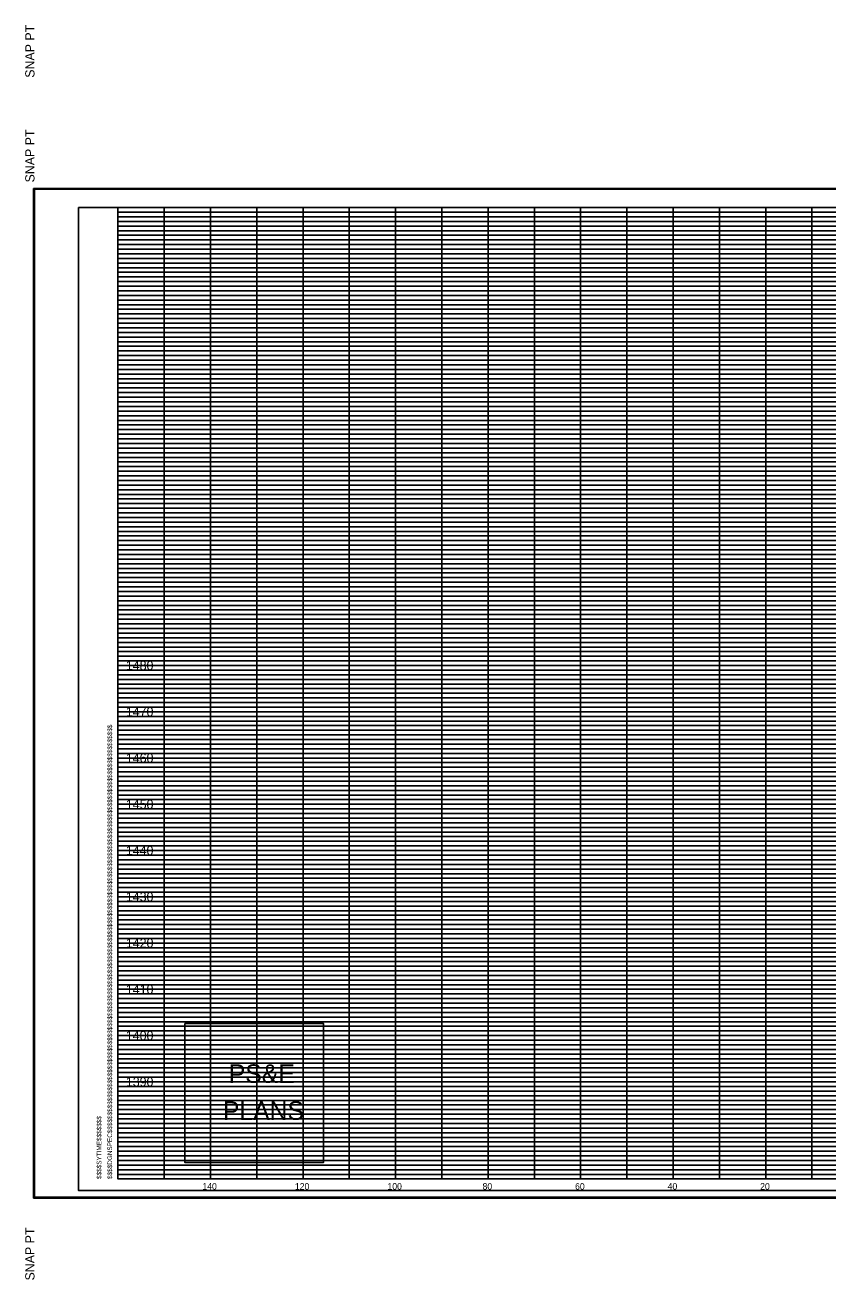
# Model space of a CAD drawing. Extents: x 980 to 2064, y 978 to 2267.
# Drawn here: x 1719.9 to 1893.4, y 978.2 to 1249.4 of the extents above; entities that cross this region are included whole.
import ezdxf

# ---------------------------------------------------------------- set-up
doc = ezdxf.new("R2010")
doc.units = 0
for name, color, linetype in [('Default', 7, 'Continuous'), ('DESIGN - SHEET - Corner Text', 7, 'Continuous'), ('DESIGN - SHEET - Light Grid', 7, 'Continuous'), ('DESIGN - SHEET - Linework', 7, 'Continuous'), ('DESIGN - SHEET - Plot Shape', 7, 'Continuous')]:
    doc.layers.add(name, color=color, linetype=linetype)

# ---------------------------------------------------------------- blocks, each defined once
blk = doc.blocks.new('XSTSHT')
at = {"layer": 'DESIGN - SHEET - Light Grid'}
for p, q in [((0, 20.9), (8, 20.9)), ((8, 20.9), (16, 20.9)), ((0, 20.8), (8, 20.8)), ((0, 20.7), (8, 20.7)), ((8, 20.8), (16, 20.8)), ((8, 20.7), (16, 20.7)), ((0, 20.6), (8, 20.6)), ((0, 20.5), (8, 20.5)), ((0, 20.4), (8, 20.4)), ((8, 20.6), (16, 20.6)), ((8, 20.5), (16, 20.5)), ((8, 20.4), (16, 20.4)), ((0, 20.3), (8, 20.3)), ((0, 20.2), (8, 20.2)), ((0, 20.1), (8, 20.1)), ((8, 20.3), (16, 20.3)), ((8, 20.2), (16, 20.2)), ((8, 20.1), (16, 20.1)), ((0, 19.9), (8, 19.9)), ((8, 19.9), (16, 19.9)), ((0, 19.8), (8, 19.8)), ((0, 19.7), (8, 19.7)), ((0, 19.6), (8, 19.6)), ((8, 19.8), (16, 19.8)), ((8, 19.7), (16, 19.7)), ((8, 19.6), (16, 19.6)), ((0, 19.5), (8, 19.5)), ((0, 19.4), (8, 19.4)), ((0, 19.3), (8, 19.3)), ((8, 19.5), (16, 19.5)), ((8, 19.4), (16, 19.4)), ((8, 19.3), (16, 19.3)), ((0, 19.2), (8, 19.2)), ((0, 19.1), (8, 19.1)), ((8, 19.2), (16, 19.2)), ((8, 19.1), (16, 19.1)), ((0, 18.9), (8, 18.9)), ((0, 18.8), (8, 18.8)), ((8, 18.9), (16, 18.9)), ((8, 18.8), (16, 18.8)), ((0, 18.7), (8, 18.7)), ((0, 18.6), (8, 18.6)), ((0, 18.5), (8, 18.5)), ((8, 18.7), (16, 18.7)), ((8, 18.6), (16, 18.6)), ((8, 18.5), (16, 18.5)), ((0, 18.4), (8, 18.4)), ((0, 18.3), (8, 18.3)), ((0, 18.2), (8, 18.2)), ((8, 18.4), (16, 18.4)), ((8, 18.3), (16, 18.3)), ((8, 18.2), (16, 18.2)), ((0, 18.1), (8, 18.1)), ((8, 18.1), (16, 18.1)), ((0, 17.9), (8, 17.9)), ((0, 17.8), (8, 17.8)), ((0, 17.7), (8, 17.7)), ((8, 17.9), (16, 17.9)), ((8, 17.8), (16, 17.8)), ((8, 17.7), (16, 17.7)), ((0, 17.6), (8, 17.6)), ((0, 17.5), (8, 17.5)), ((0, 17.4), (8, 17.4)), ((8, 17.6), (16, 17.6)), ((8, 17.5), (16, 17.5)), ((8, 17.4), (16, 17.4)), ((0, 17.3), (8, 17.3)), ((0, 17.2), (8, 17.2)), ((0, 17.1), (8, 17.1)), ((8, 17.3), (16, 17.3)), ((8, 17.2), (16, 17.2)), ((8, 17.1), (16, 17.1)), ((0, 16.9), (8, 16.9)), ((8, 16.9), (16, 16.9)), ((0, 16.8), (8, 16.8)), ((0, 16.7), (8, 16.7)), ((0, 16.6), (8, 16.6)), ((8, 16.8), (16, 16.8)), ((8, 16.7), (16, 16.7)), ((8, 16.6), (16, 16.6)), ((0, 16.5), (8, 16.5)), ((0, 16.4), (8, 16.4)), ((0, 16.3), (8, 16.3)), ((8, 16.5), (16, 16.5)), ((8, 16.4), (16, 16.4)), ((8, 16.3), (16, 16.3)), ((0, 16.2), (8, 16.2)), ((0, 16.1), (8, 16.1)), ((8, 16.2), (16, 16.2)), ((8, 16.1), (16, 16.1)), ((0, 15.9), (8, 15.9)), ((0, 15.8), (8, 15.8)), ((8, 15.9), (16, 15.9)), ((8, 15.8), (16, 15.8)), ((0, 15.7), (8, 15.7)), ((0, 15.6), (8, 15.6)), ((0, 15.5), (8, 15.5)), ((8, 15.7), (16, 15.7)), ((8, 15.6), (16, 15.6)), ((8, 15.5), (16, 15.5)), ((0, 15.4), (8, 15.4)), ((0, 15.3), (8, 15.3)), ((0, 15.2), (8, 15.2)), ((8, 15.4), (16, 15.4)), ((8, 15.3), (16, 15.3)), ((8, 15.2), (16, 15.2)), ((0, 15.1), (8, 15.1)), ((8, 15.1), (16, 15.1)), ((0, 14.9), (8, 14.9)), ((0, 14.8), (8, 14.8)), ((0, 14.7), (8, 14.7)), ((8, 14.9), (16, 14.9)), ((8, 14.8), (16, 14.8)), ((8, 14.7), (16, 14.7)), ((0, 14.6), (8, 14.6)), ((0, 14.5), (8, 14.5)), ((0, 14.4), (8, 14.4)), ((8, 14.6), (16, 14.6)), ((8, 14.5), (16, 14.5)), ((8, 14.4), (16, 14.4)), ((0, 14.3), (8, 14.3)), ((0, 14.2), (8, 14.2)), ((8, 14.3), (16, 14.3)), ((8, 14.2), (16, 14.2)), ((0, 14.1), (8, 14.1)), ((0, 13.9), (8, 13.9)), ((8, 14.1), (16, 14.1)), ((8, 13.9), (16, 13.9)), ((0, 13.8), (8, 13.8)), ((0, 13.7), (8, 13.7)), ((0, 13.6), (8, 13.6)), ((8, 13.8), (16, 13.8)), ((8, 13.7), (16, 13.7)), ((8, 13.6), (16, 13.6)), ((0, 13.5), (8, 13.5)), ((0, 13.4), (8, 13.4)), ((0, 13.3), (8, 13.3)), ((8, 13.5), (16, 13.5)), ((8, 13.4), (16, 13.4)), ((8, 13.3), (16, 13.3)), ((0, 13.2), (8, 13.2)), ((0, 13.1), (8, 13.1)), ((8, 13.2), (16, 13.2)), ((8, 13.1), (16, 13.1)), ((0, 12.9), (8, 12.9)), ((0, 12.8), (8, 12.8)), ((8, 12.9), (16, 12.9)), ((8, 12.8), (16, 12.8)), ((0, 12.7), (8, 12.7)), ((0, 12.6), (8, 12.6)), ((0, 12.5), (8, 12.5)), ((8, 12.7), (16, 12.7)), ((8, 12.6), (16, 12.6)), ((8, 12.5), (16, 12.5)), ((0, 12.4), (8, 12.4)), ((0, 12.3), (8, 12.3)), ((8, 12.4), (16, 12.4)), ((8, 12.3), (16, 12.3)), ((0, 12.2), (8, 12.2)), ((0, 12.1), (8, 12.1)), ((8, 12.2), (16, 12.2)), ((8, 12.1), (16, 12.1)), ((0, 11.9), (8, 11.9)), ((0, 11.8), (8, 11.8)), ((0, 11.7), (8, 11.7)), ((8, 11.9), (16, 11.9)), ((8, 11.8), (16, 11.8)), ((8, 11.7), (16, 11.7)), ((0, 11.6), (8, 11.6)), ((0, 11.5), (8, 11.5)), ((0, 11.4), (8, 11.4)), ((8, 11.6), (16, 11.6)), ((8, 11.5), (16, 11.5)), ((8, 11.4), (16, 11.4)), ((0, 11.3), (8, 11.3)), ((0, 11.2), (8, 11.2)), ((8, 11.3), (16, 11.3)), ((8, 11.2), (16, 11.2)), ((0, 11.1), (8, 11.1)), ((0, 10.9), (8, 10.9)), ((8, 11.1), (16, 11.1)), ((8, 10.9), (16, 10.9)), ((0, 10.8), (8, 10.8)), ((0, 10.7), (8, 10.7)), ((0, 10.6), (8, 10.6)), ((8, 10.8), (16, 10.8)), ((8, 10.7), (16, 10.7)), ((8, 10.6), (16, 10.6)), ((0, 10.5), (8, 10.5)), ((0, 10.4), (8, 10.4)), ((8, 10.5), (16, 10.5)), ((8, 10.4), (16, 10.4)), ((0, 10.3), (8, 10.3)), ((0, 10.2), (8, 10.2)), ((0, 10.1), (8, 10.1)), ((8, 10.3), (16, 10.3)), ((8, 10.2), (16, 10.2)), ((8, 10.1), (16, 10.1)), ((0, 9.9), (8, 9.9)), ((0, 9.8), (8, 9.8)), ((8, 9.9), (16, 9.9)), ((8, 9.8), (16, 9.8)), ((0, 9.7), (8, 9.7)), ((0, 9.6), (8, 9.6)), ((0, 9.5), (8, 9.5)), ((8, 9.7), (16, 9.7)), ((8, 9.6), (16, 9.6)), ((8, 9.5), (16, 9.5)), ((0, 9.4), (8, 9.4)), ((0, 9.3), (8, 9.3)), ((8, 9.4), (16, 9.4)), ((8, 9.3), (16, 9.3)), ((0, 9.2), (8, 9.2)), ((0, 9.1), (8, 9.1)), ((8, 9.2), (16, 9.2)), ((8, 9.1), (16, 9.1)), ((0, 8.9), (8, 8.9)), ((0, 8.8), (8, 8.8)), ((0, 8.7), (8, 8.7)), ((8, 8.9), (16, 8.9)), ((8, 8.8), (16, 8.8)), ((8, 8.7), (16, 8.7)), ((0, 8.6), (8, 8.6)), ((0, 8.5), (8, 8.5)), ((8, 8.6), (16, 8.6)), ((8, 8.5), (16, 8.5)), ((0, 8.4), (8, 8.4)), ((0, 8.3), (8, 8.3)), ((0, 8.2), (8, 8.2)), ((8, 8.4), (16, 8.4)), ((8, 8.3), (16, 8.3)), ((8, 8.2), (16, 8.2)), ((0, 8.1), (8, 8.1)), ((0, 7.9), (8, 7.9)), ((8, 8.1), (16, 8.1)), ((8, 7.9), (16, 7.9)), ((0, 7.8), (8, 7.8)), ((0, 7.7), (8, 7.7)), ((0, 7.6), (8, 7.6)), ((8, 7.8), (16, 7.8)), ((8, 7.7), (16, 7.7)), ((8, 7.6), (16, 7.6)), ((0, 7.5), (8, 7.5)), ((0, 7.4), (8, 7.4)), ((8, 7.5), (16, 7.5)), ((8, 7.4), (16, 7.4)), ((0, 7.3), (8, 7.3)), ((0, 7.2), (8, 7.2)), ((0, 7.1), (8, 7.1)), ((8, 7.3), (16, 7.3)), ((8, 7.2), (16, 7.2)), ((8, 7.1), (16, 7.1)), ((0, 6.9), (8, 6.9)), ((0, 6.8), (8, 6.8)), ((8, 6.9), (16, 6.9)), ((8, 6.8), (16, 6.8)), ((0, 6.7), (8, 6.7)), ((0, 6.6), (8, 6.6)), ((8, 6.7), (16, 6.7)), ((8, 6.6), (16, 6.6)), ((0, 6.5), (8, 6.5)), ((0, 6.4), (8, 6.4)), ((0, 6.3), (8, 6.3)), ((8, 6.5), (16, 6.5)), ((8, 6.4), (16, 6.4)), ((8, 6.3), (16, 6.3)), ((0, 6.2), (8, 6.2)), ((0, 6.1), (8, 6.1)), ((8, 6.2), (16, 6.2)), ((8, 6.1), (16, 6.1)), ((0, 5.9), (8, 5.9)), ((0, 5.8), (8, 5.8)), ((0, 5.7), (8, 5.7)), ((8, 5.9), (16, 5.9)), ((8, 5.8), (16, 5.8)), ((8, 5.7), (16, 5.7)), ((0, 5.6), (8, 5.6)), ((0, 5.5), (8, 5.5)), ((8, 5.6), (16, 5.6)), ((8, 5.5), (16, 5.5)), ((0, 5.4), (8, 5.4)), ((0, 5.3), (8, 5.3)), ((0, 5.2), (8, 5.2)), ((8, 5.4), (16, 5.4)), ((8, 5.3), (16, 5.3)), ((8, 5.2), (16, 5.2)), ((0, 5.1), (8, 5.1)), ((0, 4.9), (8, 4.9)), ((8, 5.1), (16, 5.1)), ((8, 4.9), (16, 4.9)), ((0, 4.8), (8, 4.8)), ((0, 4.7), (8, 4.7)), ((8, 4.8), (16, 4.8)), ((8, 4.7), (16, 4.7)), ((0, 4.6), (8, 4.6)), ((0, 4.5), (8, 4.5)), ((0, 4.4), (8, 4.4)), ((8, 4.6), (16, 4.6)), ((8, 4.5), (16, 4.5)), ((8, 4.4), (16, 4.4)), ((0, 4.3), (8, 4.3)), ((0, 4.2), (8, 4.2)), ((0, 4.1), (8, 4.1)), ((8, 4.3), (16, 4.3)), ((8, 4.2), (16, 4.2)), ((8, 4.1), (16, 4.1)), ((0, 3.9), (8, 3.9)), ((0, 3.8), (8, 3.8)), ((8, 3.9), (16, 3.9)), ((8, 3.8), (16, 3.8)), ((0, 3.7), (8, 3.7)), ((0, 3.6), (8, 3.6)), ((8, 3.7), (16, 3.7)), ((8, 3.6), (16, 3.6)), ((0, 3.5), (8, 3.5)), ((0, 3.4), (8, 3.4)), ((0, 3.3), (8, 3.3)), ((8, 3.5), (16, 3.5)), ((8, 3.4), (16, 3.4)), ((8, 3.3), (16, 3.3)), ((0, 3.2), (8, 3.2)), ((0, 3.1), (8, 3.1)), ((8, 3.2), (16, 3.2)), ((8, 3.1), (16, 3.1)), ((0, 2.9), (8, 2.9)), ((0, 2.8), (8, 2.8)), ((8, 2.9), (16, 2.9)), ((8, 2.8), (16, 2.8)), ((0, 2.7), (8, 2.7)), ((0, 2.6), (8, 2.6)), ((0, 2.5), (8, 2.5)), ((8, 2.7), (16, 2.7)), ((8, 2.6), (16, 2.6)), ((8, 2.5), (16, 2.5)), ((0, 2.4), (8, 2.4)), ((0, 2.3), (8, 2.3)), ((0, 2.2), (8, 2.2)), ((8, 2.4), (16, 2.4)), ((8, 2.3), (16, 2.3)), ((8, 2.2), (16, 2.2)), ((0, 2.1), (8, 2.1)), ((0, 1.9), (8, 1.9)), ((8, 2.1), (16, 2.1)), ((8, 1.9), (16, 1.9)), ((0, 1.8), (8, 1.8)), ((0, 1.7), (8, 1.7)), ((8, 1.8), (16, 1.8)), ((8, 1.7), (16, 1.7)), ((0, 1.6), (8, 1.6)), ((0, 1.5), (8, 1.5)), ((0, 1.4), (8, 1.4)), ((8, 1.6), (16, 1.6)), ((8, 1.5), (16, 1.5)), ((8, 1.4), (16, 1.4)), ((0, 1.3), (8, 1.3)), ((0, 1.2), (8, 1.2)), ((0, 1.1), (8, 1.1)), ((8, 1.3), (16, 1.3)), ((8, 1.2), (16, 1.2)), ((8, 1.1), (16, 1.1)), ((0, 0.9), (8, 0.9)), ((8, 0.9), (16, 0.9)), ((0, 0.8), (8, 0.8)), ((0, 0.7), (8, 0.7)), ((0, 0.6), (8, 0.6)), ((8, 0.8), (16, 0.8)), ((8, 0.7), (16, 0.7)), ((8, 0.6), (16, 0.6)), ((0, 0.5), (8, 0.5)), ((0, 0.4), (8, 0.4)), ((0, 0.3), (8, 0.3)), ((8, 0.5), (16, 0.5)), ((8, 0.4), (16, 0.4)), ((8, 0.3), (16, 0.3)), ((0, 0.2), (8, 0.2)), ((0, 0.1), (8, 0.1)), ((8, 0.2), (16, 0.2)), ((8, 0.1), (16, 0.1))]:
    blk.add_line(p, q, dxfattribs=at)
at = {"layer": 'DESIGN - SHEET - Linework'}
for p, q in [((-1.823, -0.414), (-1.823, 21.414)), ((-1.823, 21.414), (32.217, 21.414)), ((1, 0), (1, 21)), ((2, 0), (2, 21)), ((3, 0), (3, 21)), ((4, 0), (4, 21)), ((5, 0), (5, 21)), ((6, 0), (6, 21)), ((7, 0), (7, 21)), ((8, 0), (8, 21)), ((9, 0), (9, 21)), ((10, 0), (10, 21)), ((11, 0), (11, 21)), ((12, 0), (12, 21)), ((13, 0), (13, 21)), ((14, 0), (14, 21)), ((15, 0), (15, 21)), ((0, 20), (28, 20)), ((0, 19), (32, 19)), ((0, 18), (32, 18)), ((0, 17), (32, 17)), ((0, 16), (32, 16)), ((0, 15), (32, 15)), ((0, 14), (32, 14)), ((0, 13), (32, 13)), ((0, 12), (32, 12)), ((0, 11), (32, 11)), ((0, 10), (32, 10)), ((0, 9), (32, 9)), ((0, 8), (32, 8)), ((0, 7), (32, 7)), ((0, 6), (32, 6)), ((0, 5), (32, 5)), ((0, 4), (32, 4)), ((0, 3), (32, 3)), ((0, 2), (32, 2)), ((0, 1), (32, 1)), ((-1.823, -0.414), (32.217, -0.414))]:
    blk.add_line(p, q, dxfattribs=at)
blk.add_lwpolyline([(0, 21), (0, 0), (32, 0), (32, 21), (0, 21)], dxfattribs=at)
at = {"layer": 'DESIGN - SHEET - Plot Shape'}
for points in [[(-1.803, 21.394), (32.197, 21.394), (32.197, -0.394), (-1.803, -0.394)], [(-0.85, 21), (32, 21), (32, -0.25), (-0.85, -0.25)]]:
    blk.add_lwpolyline(points, close=True, dxfattribs=at)
at = {"layer": 'DESIGN - SHEET - Corner Text'}
for s, height, p in [('  SNAP PT', 0.2, (-1.803, 21.394)), ('$$$$DGNSPEC$$$$$$$$$$$$$$$$$$$$$$$$$$$$$$$$$$$$$$$$$$$$$$$$$$$$$$$$$$$$$$$$$$$$$$$$$$$$$$$$$$$$$$$$$$$$$$$$$$$$$$$$$$$$$$$$$$$', 0.100002, (-0.126, 0)), ('$$$$SYTIME$$$$$$$', 0.1, (-0.358, 0)), ('SNAP PT  ', 0.2, (-1.803, -2.194))]:
    blk.add_text(s, height=height, rotation=90, dxfattribs=at).set_placement(p)

msp = doc.modelspace()

# ---------------------------------------------------------------- linework, layer by layer
at = {"layer": 'DESIGN - SHEET - Corner Text'}
msp.add_lwpolyline([(1754.44, 1033.59), (1754.44, 1003.59), (1784.44, 1003.59), (1784.44, 1033.59)], close=True, dxfattribs=at)

# ---------------------------------------------------------------- block references
at = {"layer": 'Default', "xscale": 10, "yscale": 10}
for p in [(1740, 1260), (1740, 1000)]:
    msp.add_blockref('XSTSHT', p, dxfattribs=at)

# ---------------------------------------------------------------- texts
at = {"layer": 'Default'}
for s, height, p in [('     1480     ', 2, (1738.01, 1110)), ('     1470     ', 2, (1738.01, 1100)), ('     1460     ', 2, (1738.01, 1090)), ('     1450     ', 2, (1738.01, 1080)), ('     1440     ', 2, (1738.01, 1070)), ('     1430     ', 2, (1738.01, 1060)), ('     1420     ', 2, (1738.01, 1050)), ('     1410     ', 2, (1738.01, 1040)), ('     1400     ', 2, (1738.01, 1030)), ('     1390     ', 2, (1738.01, 1020)), ('     140     ', 1.4, (1755.65, 997.7)), ('     120     ', 1.4, (1775.65, 997.7)), ('     100     ', 1.4, (1795.65, 997.7)), ('     80     ', 1.4, (1816.2, 997.7)), ('     60     ', 1.4, (1836.2, 997.7)), ('     40     ', 1.4, (1856.2, 997.7)), ('     20     ', 1.4, (1876.2, 997.7))]:
    msp.add_text(s, height=height, dxfattribs=at).set_placement(p)
at = {"layer": 'DESIGN - SHEET - Corner Text'}
for s, p in [('PS&E', (1763.96, 1020.77)), ('PLANS', (1762.68, 1012.77))]:
    msp.add_text(s, height=4, dxfattribs=at).set_placement(p)

doc.saveas('drawing.dxf')
